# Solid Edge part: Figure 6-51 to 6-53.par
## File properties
Author: Ashutosh-CADCIM
Template: Iso Metric Part.par
Last saved by: Ashutosh-CADCIM
Revision: 1
Application: Solid Edge
Accuracy: 0.990
Username: Ashutosh-CADCIM
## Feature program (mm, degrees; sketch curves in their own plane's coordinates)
sketch for "unnamed RevolvedProtrusion 1" plane through (0, 0, 0) normal (0, -1, 0) x-axis (1, 0, 0)
  line (24.112, 0) -> (24.112, 20)
  line (24.112, 20) -> (124.112, 20)
  line (124.112, 20) -> (124.112, 30)
  line (124.112, 30) -> (126.112, 30)
  line (126.112, 30) -> (126.112, 0)
  line (126.112, 0) -> (24.112, 0)
revolve "unnamed RevolvedProtrusion 1" add finite 360 deg about sketch line (0, 0) -> (0, 105.6174)
sketch for "unnamed Cutout 1" plane through (0, 0, 20) normal (0, 0, 1) x-axis (0, 1, 0)
  circle centre (-85.7001, 0) radius 10
extrude "unnamed Cutout 1" cut finite 82.3041 along -normal
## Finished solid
Body 1: solid body, 7 faces, 8 edges, 0 vertices.
  Faces by surface: cylinder 4, plane 3
  Edges by curve: circle 8
Bounding box of the edges (mm): 252.224 x 252.224 x 30.000, from (-126.112, -126.112, 0) to (126.112, 126.112, 30).
Cylindrical faces by radius (mm): R10 x1, R24.112 x1, R124.112 x1, R126.112 x1
Planar faces by outward normal: +z 2, -z 1
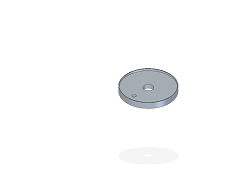
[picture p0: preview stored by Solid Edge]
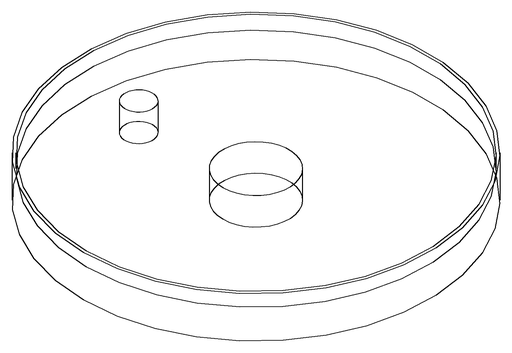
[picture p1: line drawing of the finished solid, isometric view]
